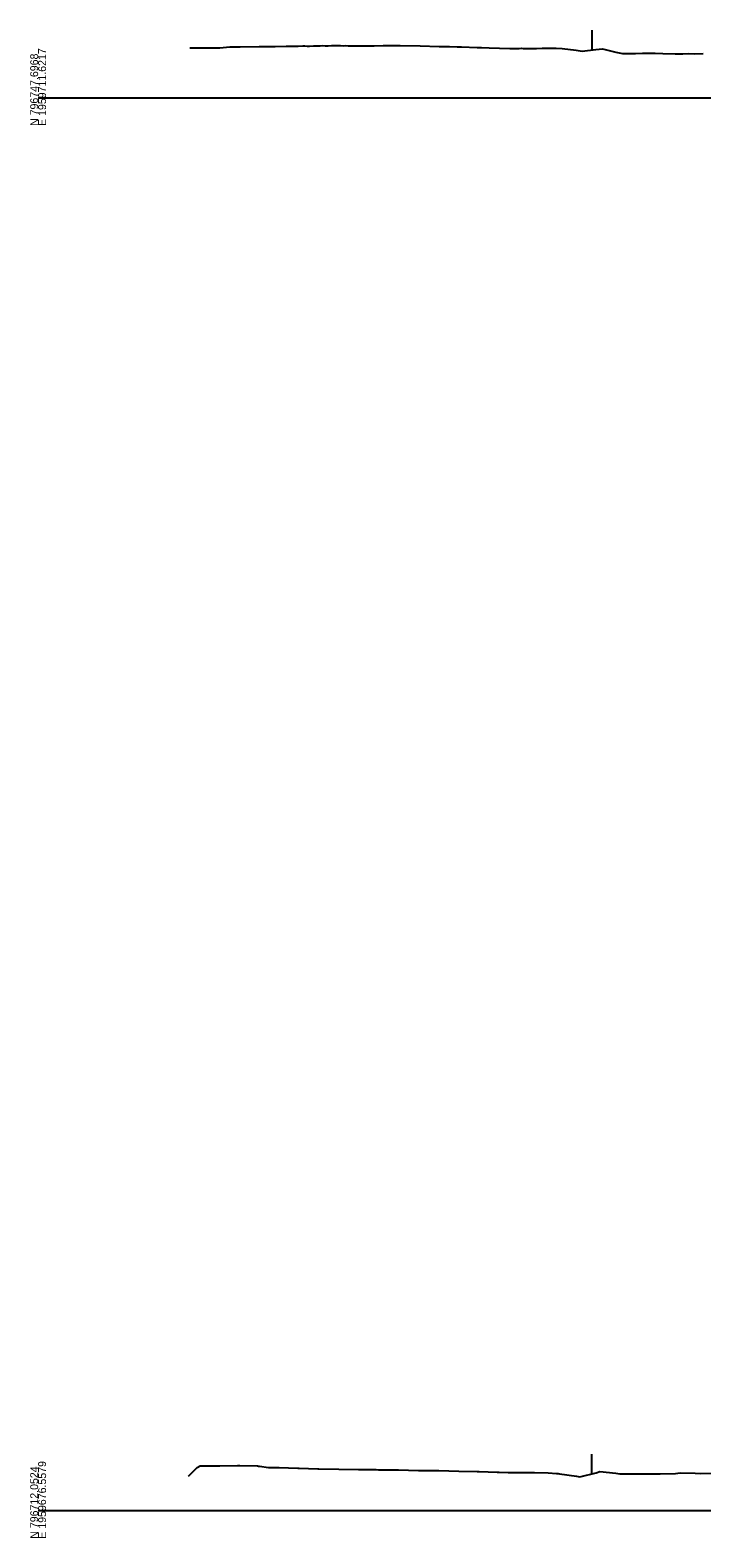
# Model space of a CAD drawing. Extents: x -4026 to 9638, y -10 to 19609.
# Drawn here: x -1003 to -765, y 4990 to 5524 of the extents above; entities that cross this region are included whole.
import ezdxf

# ---------------------------------------------------------------- set-up
doc = ezdxf.new("R2010")
doc.units = 0
for name, color, linetype in [('Default', 7, 'Continuous'), ('RD_EX_Fence_Other', 7, 'Continuous'), ('RD_GPK_XS_Cell', 7, 'Continuous'), ('RD_XS_ExGround', 7, 'Continuous')]:
    doc.layers.add(name, color=color, linetype=linetype)

msp = doc.modelspace()

# ---------------------------------------------------------------- linework, layer by layer
at = {"layer": 'RD_EX_Fence_Other'}
for p, q in [((-803.9, 5523.9), (-803.9, 5516.9)), ((-804, 5019.96), (-804, 5012.96))]:
    msp.add_line(p, q, dxfattribs=at)
at = {"layer": 'RD_GPK_XS_Cell'}
for p, q in [((-1000, 5500), (-650, 5500)), ((-1000, 5000), (-650, 5000))]:
    msp.add_line(p, q, dxfattribs=at)
at = {"layer": 'RD_XS_ExGround'}
for points in [[(-946.28, 5517.64), (-942.73, 5517.59), (-941.31, 5517.61), (-935.62, 5517.69), (-932.13, 5518), (-928.49, 5518.03), (-921.69, 5518.06), (-921.36, 5518.06), (-917.43, 5518.12), (-916.99, 5518.13), (-916.52, 5518.14), (-916.03, 5518.15), (-912.21, 5518.2), (-911.79, 5518.21), (-911.35, 5518.21), (-910.87, 5518.22), (-910.36, 5518.22), (-909.82, 5518.23), (-909.24, 5518.25), (-908.62, 5518.27), (-907.96, 5518.28), (-906.3, 5518.29), (-905.52, 5518.31), (-904.7, 5518.28), (-903.85, 5518.28), (-902.49, 5518.32), (-901.74, 5518.34), (-900.94, 5518.37), (-900.11, 5518.39), (-899.24, 5518.41), (-898.3, 5518.36), (-897.32, 5518.38), (-896.1, 5518.47), (-895.4, 5518.51), (-893.95, 5518.51), (-892.88, 5518.51), (-891.9, 5518.38), (-891, 5518.41), (-890.18, 5518.37), (-889.43, 5518.35), (-888.73, 5518.35), (-888.08, 5518.37), (-885.97, 5518.29), (-885.19, 5518.31), (-884.46, 5518.32), (-883.79, 5518.33), (-883.15, 5518.33), (-882.56, 5518.35), (-881.99, 5518.37), (-881.47, 5518.39), (-880.97, 5518.4), (-877.76, 5518.42), (-877.18, 5518.42), (-876.63, 5518.42), (-872.76, 5518.5), (-871.82, 5518.5), (-864.72, 5518.36), (-857.98, 5518.15), (-857.19, 5518.15), (-854.35, 5518.07), (-851.55, 5517.98), (-850.06, 5517.95), (-844.54, 5517.8), (-842.93, 5517.75), (-840.21, 5517.68), (-832.94, 5517.45), (-832.29, 5517.43), (-830.91, 5517.43), (-829.59, 5517.45), (-828.77, 5517.48), (-828.2, 5517.46), (-823.5, 5517.46), (-821.54, 5517.47), (-816.48, 5517.47), (-814.41, 5517.36), (-809.47, 5516.76), (-807.28, 5516.48), (-802.45, 5517.08), (-800.15, 5517.31), (-795.44, 5516.07), (-793.02, 5515.58), (-788.43, 5515.69), (-785.9, 5515.77), (-781.41, 5515.72), (-778.77, 5515.63), (-774.4, 5515.51), (-771.64, 5515.52), (-769.49, 5515.58), (-767.39, 5515.56), (-764.51, 5515.58)], [(-946.69, 5012.19), (-943.67, 5015.24), (-942.64, 5015.82), (-936.54, 5015.83), (-935.63, 5015.83), (-929.41, 5015.86), (-929.01, 5015.87), (-928.61, 5015.86), (-922.28, 5015.74), (-921.94, 5015.73), (-921.6, 5015.69), (-918.4, 5015.15), (-915.15, 5015.16), (-914.58, 5015.15), (-908.02, 5015.02), (-907.57, 5015.01), (-900.89, 5014.78), (-900.56, 5014.77), (-893.54, 5014.6), (-886.53, 5014.55), (-880.33, 5014.44), (-879.5, 5014.43), (-872.37, 5014.32), (-865.24, 5014.18), (-858.47, 5014.16), (-858.11, 5014.15), (-850.98, 5013.95), (-844.45, 5013.77), (-843.85, 5013.76), (-837.43, 5013.54), (-836.72, 5013.52), (-833.55, 5013.47), (-825.93, 5013.47), (-825.62, 5013.47), (-824.19, 5013.43), (-819.4, 5013.33), (-816.39, 5013.1), (-815.87, 5013.06), (-815.33, 5013), (-809.38, 5012.15), (-808.2, 5011.91), (-802.36, 5013.37), (-801.07, 5013.79), (-795.35, 5013.15), (-794.65, 5013.03), (-793.94, 5013.01), (-788.34, 5012.99), (-786.81, 5012.97), (-784.05, 5012.93), (-781.32, 5013.01), (-780.51, 5013.02), (-779.68, 5013.02), (-774.31, 5013.12), (-772.55, 5013.27), (-767.3, 5013.19), (-765.42, 5013.11), (-760.28, 5013.19)]]:
    msp.add_lwpolyline(points, dxfattribs=at)

# ---------------------------------------------------------------- texts
at = {"layer": 'Default'}
for p in [(-1000, 5500), (-1000, 5000)]:
    msp.add_text('-', height=0.0001, dxfattribs=at).set_placement(p)
at = {"layer": 'RD_GPK_XS_Cell'}
for s, p in [('N 796747.6968', (-1000, 5490)), ('E 1959711.6217', (-997.2, 5490)), ('E 1959676.5579', (-997.2, 4990)), ('N 796712.0524', (-1000, 4990))]:
    msp.add_text(s, height=2.8, rotation=90, dxfattribs=at).set_placement(p)

doc.saveas('drawing.dxf')
